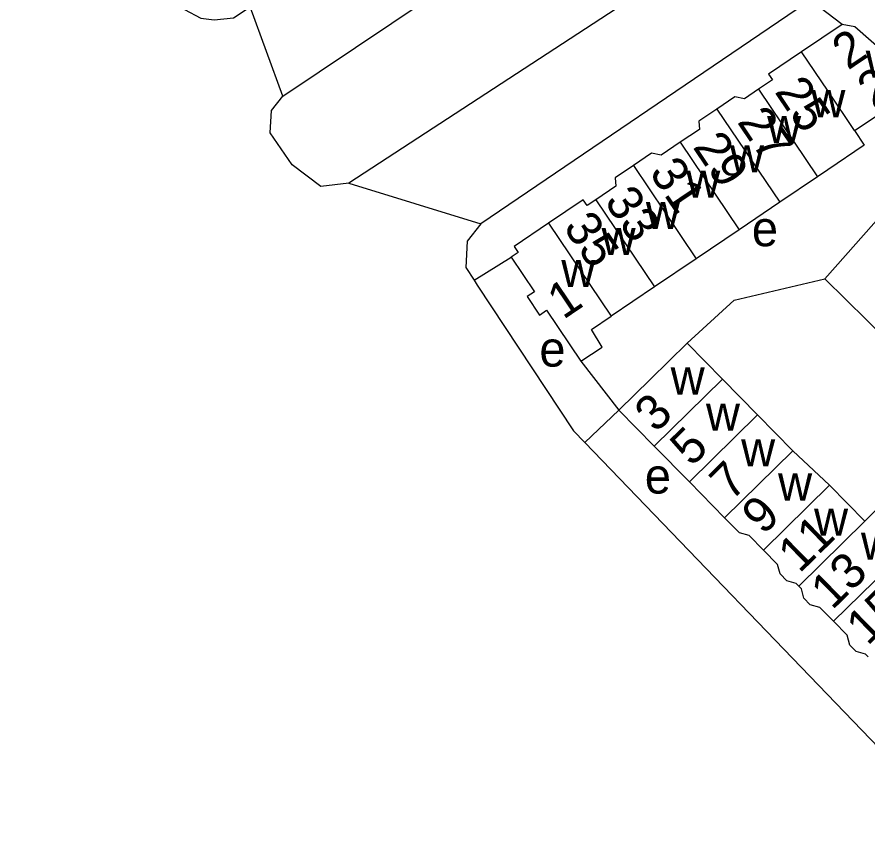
# Model space of a CAD drawing. Extents: x 159261 to 160849, y 382514 to 384534.
# Drawn here: x 160379.1 to 160475.7, y 382775 to 382869.3 of the extents above; entities that cross this region are included whole.
import ezdxf

# ---------------------------------------------------------------- set-up
doc = ezdxf.new("R2010")
doc.units = 0
for name, color, linetype in [('BLT_Basislijn', 7, 'Continuous'), ('BLT_Bebouwing', 7, 'Continuous'), ('BLT_Centroide', 7, 'Continuous'), ('BLT_Huisnummer', 7, 'Continuous'), ('BLT_Huisnummer_ tussenligend', 7, 'Continuous'), ('BLT_Huisnummer_reeks', 7, 'Continuous'), ('BLT_Onderverdeling_panden', 7, 'Continuous'), ('BLT_Vlakafsluiter', 7, 'Continuous')]:
    doc.layers.add(name, color=color, linetype=linetype)

msp = doc.modelspace()

# ---------------------------------------------------------------- linework, layer by layer
at = {"layer": 'BLT_Basislijn'}
for p, q in [((160430.961, 382839.459), (160435.176, 382842.086)), ((160502.649, 382808.144), (160470.801, 382839.624)), ((160443.09, 382830.271), (160447.406, 382824.732)), ((160443.524, 382821.063), (160447.406, 382824.732)), ((160443.524, 382821.063), (160487.839, 382775.037))]:
    msp.add_line(p, q, dxfattribs=at)
for points in [[(160434.002, 382876.966), (160453.084, 382889.777), (160456.01, 382891.647), (160461.299, 382894.808), (160465.785, 382887.797), (160468.626, 382883.794), (160456.569, 382876.483), (160416.746, 382850.468)], [(160379.065, 382888.651), (160398.064, 382870.186), (160399.954, 382869.225), (160401.455, 382869.022), (160403.63, 382869.263), (160405.544, 382870.498)], [(160409.259, 382860.359), (160434.002, 382876.966)], [(160472.77, 382868.495), (160470.2, 382870.415), (160467.65, 382870.218), (160431.718, 382845.888)], [(160416.746, 382850.468), (160413.553, 382850.118), (160410.309, 382852.554), (160407.796, 382856.211), (160407.968, 382858.737), (160409.259, 382860.359)], [(160470.801, 382839.624), (160477.507, 382847.24)], [(160431.718, 382845.888), (160430.186, 382843.916), (160430.027, 382840.914), (160430.961, 382839.459)], [(160455.146, 382832.332), (160460.51, 382837.219), (160470.801, 382839.624)], [(160430.961, 382839.459), (160431.305, 382838.923), (160442.246, 382822.391), (160443.524, 382821.063)]]:
    msp.add_lwpolyline(points, dxfattribs=at)
at = {"layer": 'BLT_Bebouwing'}
for p, q in [((160472.77, 382868.495), (160468.142, 382865.378)), ((160469.937, 382851.206), (160465.659, 382848.314)), ((160465.659, 382848.314), (160461.059, 382845.205)), ((160461.059, 382845.205), (160456.18, 382841.906)), ((160456.18, 382841.906), (160451.443, 382838.704)), ((160451.443, 382838.704), (160446.54, 382835.389)), ((160455.146, 382832.332), (160459.162, 382828.242)), ((160459.162, 382828.242), (160463.155, 382824.175)), ((160451.421, 382820.643), (160447.406, 382824.732)), ((160463.155, 382824.175), (160467.148, 382820.107)), ((160455.414, 382816.576), (160451.421, 382820.643)), ((160467.148, 382820.107), (160471.31, 382816.205)), ((160459.408, 382812.508), (160455.414, 382816.576)), ((160471.31, 382816.205), (160475.318, 382812.121))]:
    msp.add_line(p, q, dxfattribs=at)
for points in [[(160477.584, 382865.247), (160474.198, 382868.217), (160472.77, 382868.495)], [(160468.142, 382865.378), (160464.394, 382862.853), (160464.827, 382862.21), (160463.242, 382861.142)], [(160463.242, 382861.142), (160461.657, 382860.074), (160460.583, 382860.283), (160458.529, 382858.899)], [(160474.156, 382856.449), (160477.173, 382858.481), (160478.61, 382856.349), (160483.777, 382859.83)], [(160458.529, 382858.899), (160456.475, 382857.516), (160456.54, 382856.579), (160454.377, 382855.121)], [(160474.156, 382856.449), (160475.263, 382854.807), (160471.121, 382852.007), (160469.937, 382851.206)], [(160454.377, 382855.121), (160452.214, 382853.664), (160451.112, 382853.879), (160449.05, 382852.49)], [(160449.05, 382852.49), (160446.989, 382851.102), (160447.055, 382850.148), (160444.769, 382848.608)], [(160444.769, 382848.608), (160443.794, 382847.951), (160443.359, 382848.596), (160439.427, 382845.947)], [(160439.427, 382845.947), (160435.496, 382843.299), (160435.959, 382842.613), (160435.176, 382842.086)], [(160435.176, 382842.086), (160437.817, 382838.166), (160436.984, 382837.605), (160438.388, 382835.52), (160439.19, 382836.06), (160443.09, 382830.271)], [(160443.09, 382830.271), (160445.488, 382831.886), (160444.296, 382833.872), (160446.54, 382835.389)], [(160447.406, 382824.732), (160450.974, 382828.235), (160455.146, 382832.332)], [(160475.318, 382812.121), (160478.014, 382814.766), (160481.952, 382810.756), (160479.258, 382808.109)], [(160463.816, 382808.848), (160462.202, 382810.492), (160461.081, 382810.804), (160459.408, 382812.508)], [(160467.82, 382804.757), (160467.517, 382805.066), (160466.473, 382805.356), (160465.706, 382806.138), (160465.43, 382807.204), (160463.816, 382808.848)], [(160471.773, 382800.761), (160470.22, 382802.343), (160469.132, 382802.645), (160468.396, 382803.394), (160468.124, 382804.448), (160467.82, 382804.757)], [(160475.718, 382796.714), (160475.419, 382797.018), (160474.335, 382797.32), (160473.616, 382798.052), (160473.325, 382799.18), (160471.773, 382800.761)]]:
    msp.add_lwpolyline(points, dxfattribs=at)
at = {"layer": 'BLT_Onderverdeling_panden'}
for p, q in [((160471.149, 382860.913), (160468.142, 382865.378)), ((160463.242, 382861.142), (160469.937, 382851.206)), ((160474.156, 382856.449), (160471.149, 382860.913)), ((160458.529, 382858.899), (160465.659, 382848.314)), ((160454.377, 382855.121), (160461.059, 382845.205)), ((160449.05, 382852.49), (160456.18, 382841.906)), ((160444.769, 382848.608), (160451.443, 382838.704)), ((160439.427, 382845.947), (160446.54, 382835.389)), ((160451.421, 382820.643), (160459.162, 382828.242)), ((160455.414, 382816.576), (160463.155, 382824.175)), ((160459.408, 382812.508), (160467.148, 382820.107)), ((160463.816, 382808.848), (160471.31, 382816.205)), ((160467.82, 382804.757), (160475.318, 382812.121)), ((160471.773, 382800.761), (160479.258, 382808.109))]:
    msp.add_line(p, q, dxfattribs=at)
at = {"layer": 'BLT_Vlakafsluiter'}
for p, q in [((160409.259, 382860.359), (160405.544, 382870.498)), ((160416.746, 382850.468), (160431.718, 382845.888))]:
    msp.add_line(p, q, dxfattribs=at)

# ---------------------------------------------------------------- texts
at = {"layer": 'BLT_Centroide'}
for s, p in [('w', (160475.422, 382862.469)), ('w', (160469.25, 382857.969)), ('w', (160464.234, 382855.047)), ('w', (160460.016, 382851.719)), ('w', (160455.047, 382848.844)), ('w', (160450.469, 382845.266)), ('e', (160462.5, 382843.327)), ('w', (160445.438, 382842.328)), ('w', (160440.859, 382838.703)), ('e', (160438.375, 382829.668)), ('w', (160453.281, 382826.5)), ('w', (160457.289, 382822.406)), ('w', (160461.281, 382818.344)), ('e', (160450.344, 382815.262)), ('w', (160465.477, 382814.469)), ('w', (160469.562, 382810.469)), ('w', (160474.891, 382807.75))]:
    msp.add_text(s, height=4, dxfattribs=at).set_placement(p)
at = {"layer": 'BLT_Huisnummer'}
for s, rotation, p in [('25', 303.964, (160465.017, 382860.861)), ('31', 303.9755, (160450.776, 382851.678)), ('35', 303.96843, (160441.016, 382845.494)), ('1', 33.95939, (160441.081, 382834.946)), ('3', 44.46964, (160451.608, 382822.055)), ('7', 44.47139, (160460.146, 382814.299)), ('11', 44.46699, (160467.901, 382806.119)), ('15', 44.47099, (160475.635, 382797.897))]:
    msp.add_text(s, height=4, rotation=rotation, dxfattribs=at).set_placement(p)
at = {"layer": 'BLT_Huisnummer_ tussenligend'}
for s, rotation, p in [('27', 303.964, (160460.767, 382857.435)), ('29', 303.964, (160455.721, 382854.598)), ('33', 303.9755, (160445.675, 382848.412)), ('5', 44.46964, (160455.649, 382818.214)), ('9', 44.47139, (160463.788, 382810.463)), ('13', 44.46699, (160471.62, 382801.962))]:
    msp.add_text(s, height=4, rotation=rotation, dxfattribs=at).set_placement(p)
at = {"layer": 'BLT_Huisnummer_reeks'}
for s, p in [('2', (160473.408, 382863.247)), ('2a-b', (160476.268, 382858.925))]:
    msp.add_text(s, height=4, rotation=33.9636, dxfattribs=at).set_placement(p)

doc.saveas('drawing.dxf')
